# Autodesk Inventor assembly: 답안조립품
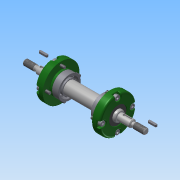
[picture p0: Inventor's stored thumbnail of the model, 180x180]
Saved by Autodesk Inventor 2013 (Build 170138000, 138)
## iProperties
Created: 2016-03
Part Number: 답안조립품
Document SubType Name: Assembly
Designer: Administrator
Author: Administrator
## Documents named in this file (8)
- C:\Users\Administrator\Desktop\460308V1028\답안조립품.iam
- C:\Users\Administrator\Desktop\460308V1028\본체.ipt
- C:\Users\Administrator\Desktop\460308V1028\베어링 15 x 32 x 9.ipt
- C:\Users\Administrator\Desktop\460308V1028\축.ipt
- C:\Users\Administrator\Desktop\460308V1028\커버.ipt
- C:\Users\Administrator\Desktop\460308V1028\볼트 M4 x 12.ipt
- C:\Users\Administrator\Desktop\460308V1028\오일 실 15 25 7.ipt
- C:\Users\Administrator\Desktop\460308V1028\키 3 x 3 x 12.ipt
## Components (10 placed, 2 different names)
1. KS B 2023 6002 - 15 x 32 x 9:1
2. KS B 2023 6002 - 15 x 32 x 9:2
3. ISO 4762 M4 x 12:2
4. ISO 4762 M4 x 12:3
5. ISO 4762 M4 x 12:4
6. ISO 4762 M4 x 12:5
7. ISO 4762 M4 x 12:1
8. ISO 4762 M4 x 12:6
9. ISO 4762 M4 x 12:7
10. ISO 4762 M4 x 12:8
